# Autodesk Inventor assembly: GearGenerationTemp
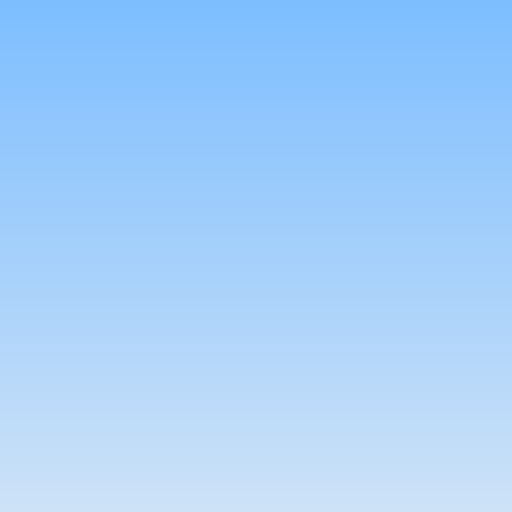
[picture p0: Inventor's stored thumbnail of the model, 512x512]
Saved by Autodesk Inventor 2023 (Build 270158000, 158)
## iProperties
Created: 2024-05
Part Number: GearGenerationTemp
Document SubType Name: Assembly
Designer: kumagai
Author: kumagai
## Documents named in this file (1)
- \\192.168.3.8\kumagai\Develop\CAD\NakataOmni\DriveUnitR3\GearGenerationTemp.iam
